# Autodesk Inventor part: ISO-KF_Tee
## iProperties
Created: 2006-07
Part Number: ISO-KF_Tee
Document SubType Name: Modeling
Designer: Administrator
Author: Administrator
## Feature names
1. Revolution1
2. Revolution4
3. Extrusion1
4. Extrusion2
5. Fillet1
